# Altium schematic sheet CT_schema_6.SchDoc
size 524 x 490 mm
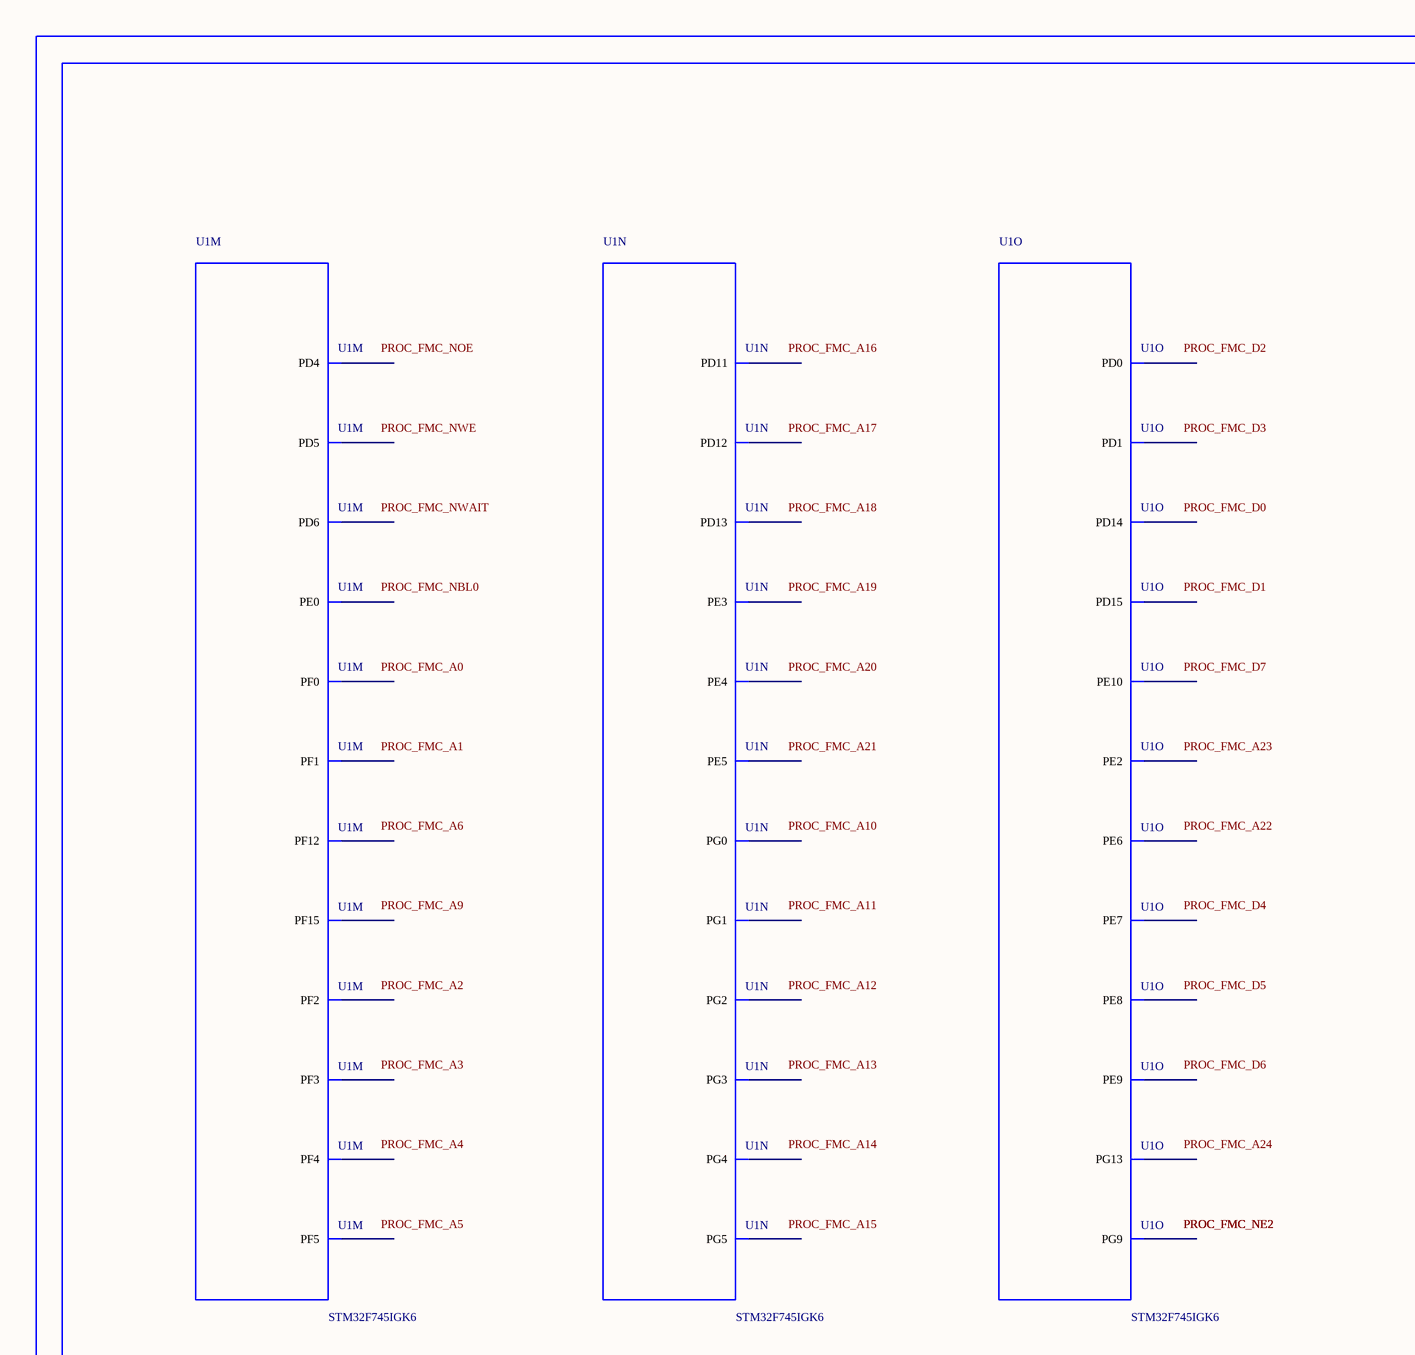
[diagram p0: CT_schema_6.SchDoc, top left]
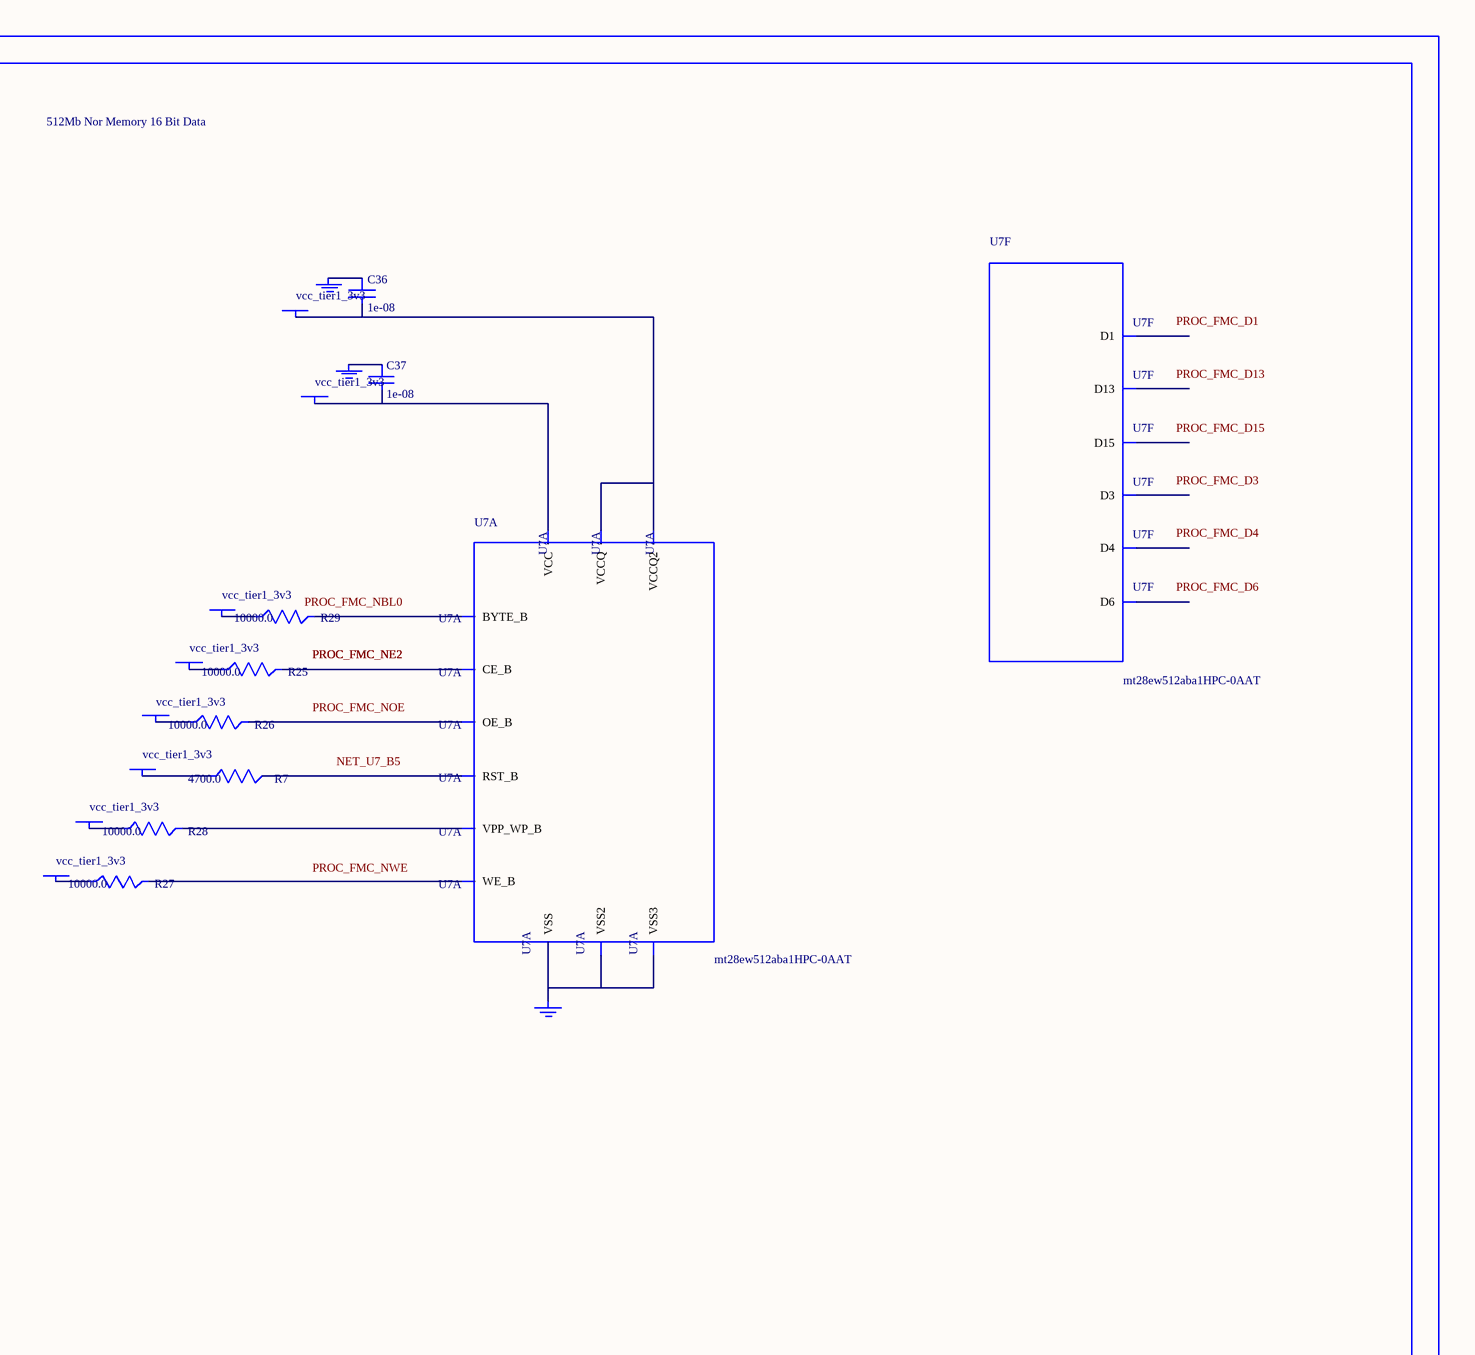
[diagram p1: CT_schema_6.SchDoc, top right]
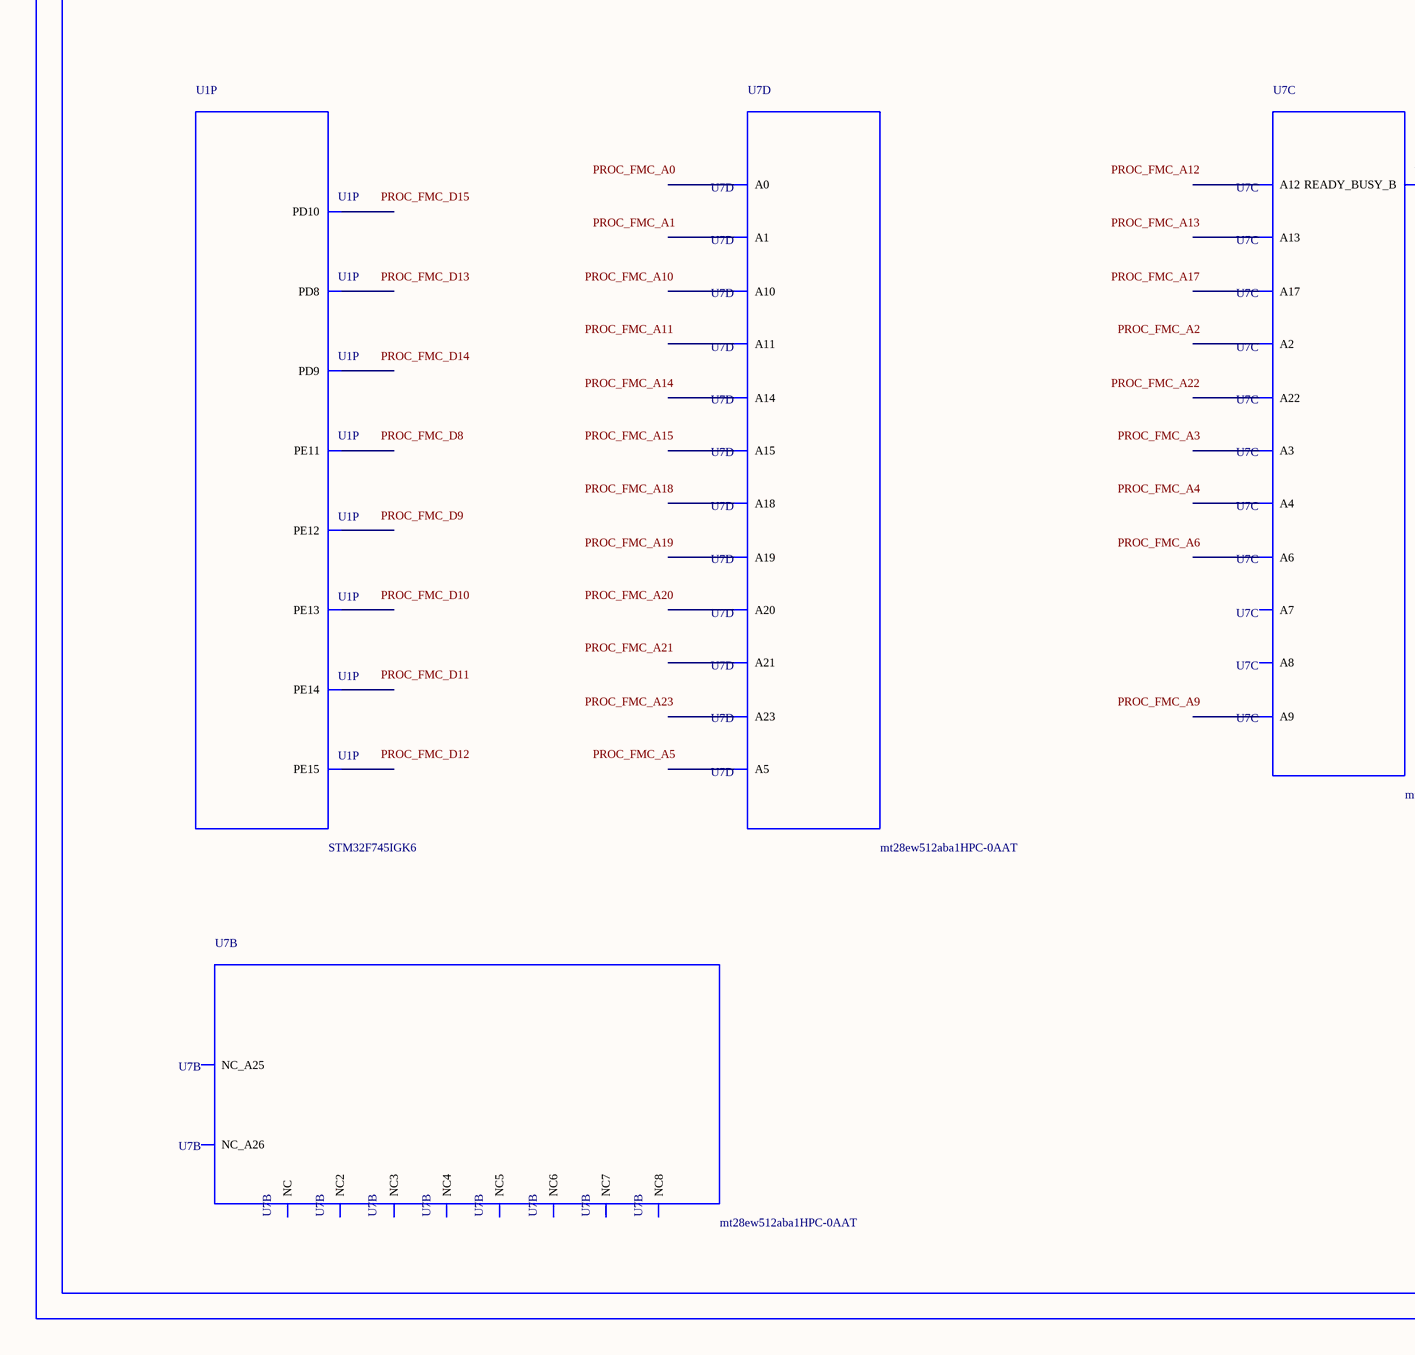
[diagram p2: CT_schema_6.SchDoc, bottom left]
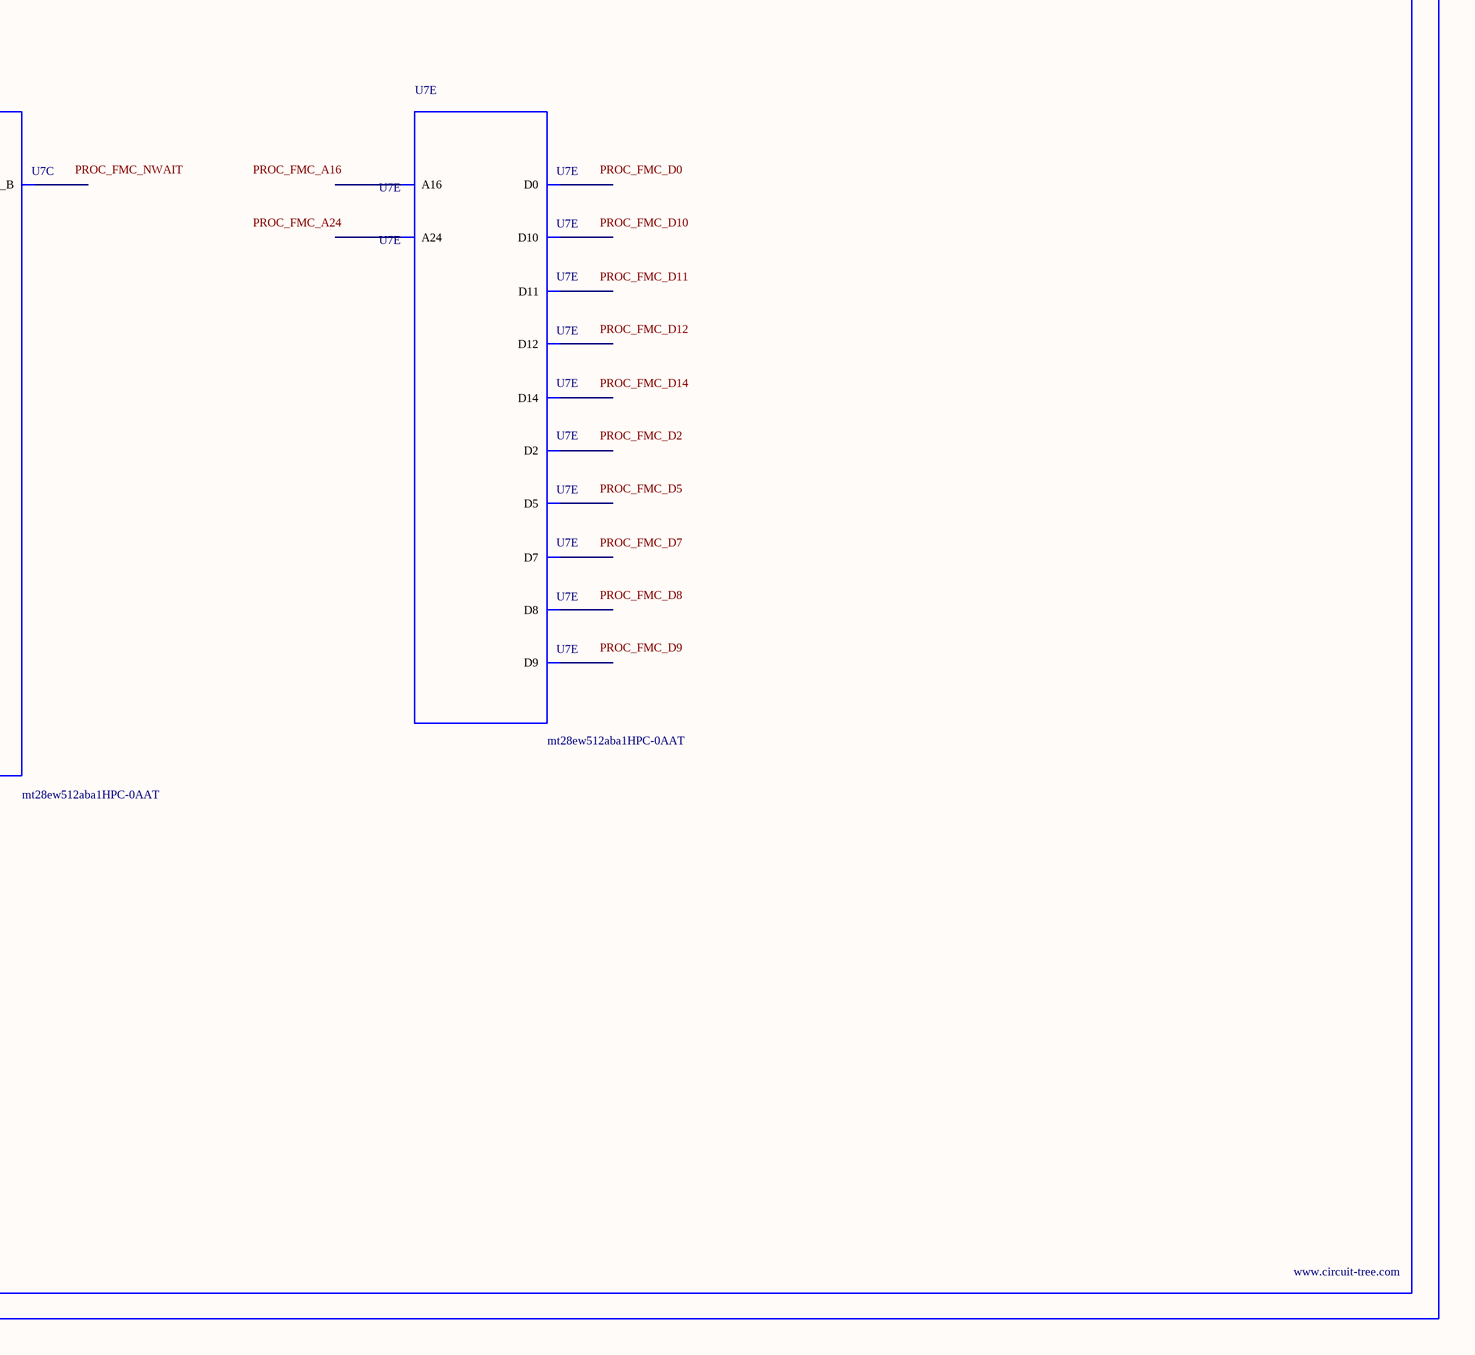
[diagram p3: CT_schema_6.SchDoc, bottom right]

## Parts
BORDER5  (no value)
C36  1e-08  [C0402]
C37  1e-08  [C0402]
GND_INSTANCE_5_0  (no value)
GND_INSTANCE_5_1  (no value)
GND_INSTANCE_5_2  (no value)
POWER_INSTANCE_5_0  vcc_tier1_3v3
POWER_INSTANCE_5_1  vcc_tier1_3v3
POWER_INSTANCE_5_2  vcc_tier1_3v3
POWER_INSTANCE_5_3  vcc_tier1_3v3
POWER_INSTANCE_5_4  vcc_tier1_3v3
POWER_INSTANCE_5_5  vcc_tier1_3v3
POWER_INSTANCE_5_6  vcc_tier1_3v3
POWER_INSTANCE_5_7  vcc_tier1_3v3
R7  4700.0  [R0603]
R25  10000.0  [R0603]
R26  10000.0  [R0603]
R27  10000.0  [R0603]
R28  10000.0  [R0603]
R29  10000.0  [R0603]
U1  STM32F745IGK6  [UFBGA176_25]  (parts M,N,O,P of 16)
U7  mt28ew512aba1HPC-0AAT  [LBGA-64]  (parts A,B,C,D,E,F of 6)

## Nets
NetC36_1: C36.1 GND_INSTANCE_5_0.0(GND)
NetC36_2: C36.2 POWER_INSTANCE_5_0.0(PWR) U7.D8(VCCQ) U7.F1(VCCQ2)
NetC37_1: C37.1 GND_INSTANCE_5_1.0(GND)
NetC37_2: C37.2 POWER_INSTANCE_5_1.0(PWR) U7.G5(VCC)
NetGND_INSTANCE_5_2_0: GND_INSTANCE_5_2.0(GND) U7.E8(VSS) U7.H2(VSS2) U7.H7(VSS3)
NetPOWER_INSTANCE_5_2_0: POWER_INSTANCE_5_2.0(PWR) R25.1
NetPOWER_INSTANCE_5_3_0: POWER_INSTANCE_5_3.0(PWR) R26.1
NetPOWER_INSTANCE_5_4_0: POWER_INSTANCE_5_4.0(PWR) R27.1
NetPOWER_INSTANCE_5_5_0: POWER_INSTANCE_5_5.0(PWR) R28.1
NetPOWER_INSTANCE_5_6_0: POWER_INSTANCE_5_6.0(PWR) R29.1
NetPOWER_INSTANCE_5_7_0: POWER_INSTANCE_5_7.0(PWR) R7.1
NetR7_2: R7.2 U7.B5(RST_B)
NetR25_2: R25.2 U7.F2(CE_B)
NetR26_2: R26.2 U7.G2(OE_B)
NetR27_2: R27.2 U7.A5(WE_B)
NetR28_2: R28.2 U7.B4(VPP_WP_B)
NetR29_2: R29.2 U7.F7(BYTE_B)

Not connected (* = marked no-connect by the designer): U1 A1(PE3) A2(PE2) A4(PE0) A8(PG13) B1(PE4) B2(PE5) B3(PE6) B11(PD6) B12(PD0) C10(PG9) C11(PD5) C12(PD1) D10(PD4) E2(PF0) H2(PF2) H3(PF1) J2(PF3) J3(PF4) K3(PF5) K13(PG5) K14(PG4) K15(PG3) L14(PD15) L15(PG2) M7(PG1) M14(PD14) M15(PD13) N7(PG0) N11(PE13) N13(PD12) N14(PD11) N15(PD10) P6(PF12) P7(PF15) P8(PE8) P9(PE9) P10(PE11) P11(PE14) P14(PD9) P15(PD8) R8(PE7) R9(PE10) R10(PE12) R11(PE15); U7 A1(NC) A2(A3) A3(A7) A4(READY_BUSY_B) A6(A9) A7(A13) A8(NC2) B1(NC_A26) B2(A4) B3(A17) B6(A8) B7(A12) B8(A22) C1(NC3) C2(A2) C3(A6) C4(A18) C5(A21) C6(A10) C7(A14) C8(A23) D1(NC4) D2(A1) D3(A5) D4(A20) D5(A19) D6(A11) D7(A15) E1(NC5) E2(A0) E3(D0) E4(D2) E5(D5) E6(D7) E7(A16) F3(D8) F4(D10) F5(D12) F6(D14) F8(A24) G1(NC6) G3(D9) G4(D11) G6(D13) G7(D15) G8(NC_A25) H1(NC7) H3(D1) H4(D3) H5(D4) H6(D6) H8(NC8)

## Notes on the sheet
- Labels drawn without touching a wire or pin: NET_U7_B5, PROC_FMC_A0, PROC_FMC_A1, PROC_FMC_A2, PROC_FMC_A3, PROC_FMC_A4, PROC_FMC_A5, PROC_FMC_A6, PROC_FMC_A9, PROC_FMC_A10, PROC_FMC_A11, PROC_FMC_A12, PROC_FMC_A13, PROC_FMC_A14, PROC_FMC_A15, PROC_FMC_A16, PROC_FMC_A17, PROC_FMC_A18, PROC_FMC_A19, PROC_FMC_A20, PROC_FMC_A21, PROC_FMC_A22, PROC_FMC_A23, PROC_FMC_A24, PROC_FMC_D0, PROC_FMC_D1, PROC_FMC_D2, PROC_FMC_D3, PROC_FMC_D4, PROC_FMC_D5, PROC_FMC_D6, PROC_FMC_D7, PROC_FMC_D8, PROC_FMC_D9, PROC_FMC_D10, PROC_FMC_D11, PROC_FMC_D12, PROC_FMC_D13, PROC_FMC_D14, PROC_FMC_D15, PROC_FMC_NBL0, PROC_FMC_NOE, PROC_FMC_NWAIT, PROC_FMC_NWE

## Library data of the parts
BORDER5 = BORDER_PAGE5
C36 C37 = C0402C103K3RAC
GND_INSTANCE_5_0-GND_INSTANCE_5_2 = GND
POWER_INSTANCE_5_0-POWER_INSTANCE_5_7 = PWR
R7 = RC0603JR-074K7L
R25-R29 = RC0603JR-0710KL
